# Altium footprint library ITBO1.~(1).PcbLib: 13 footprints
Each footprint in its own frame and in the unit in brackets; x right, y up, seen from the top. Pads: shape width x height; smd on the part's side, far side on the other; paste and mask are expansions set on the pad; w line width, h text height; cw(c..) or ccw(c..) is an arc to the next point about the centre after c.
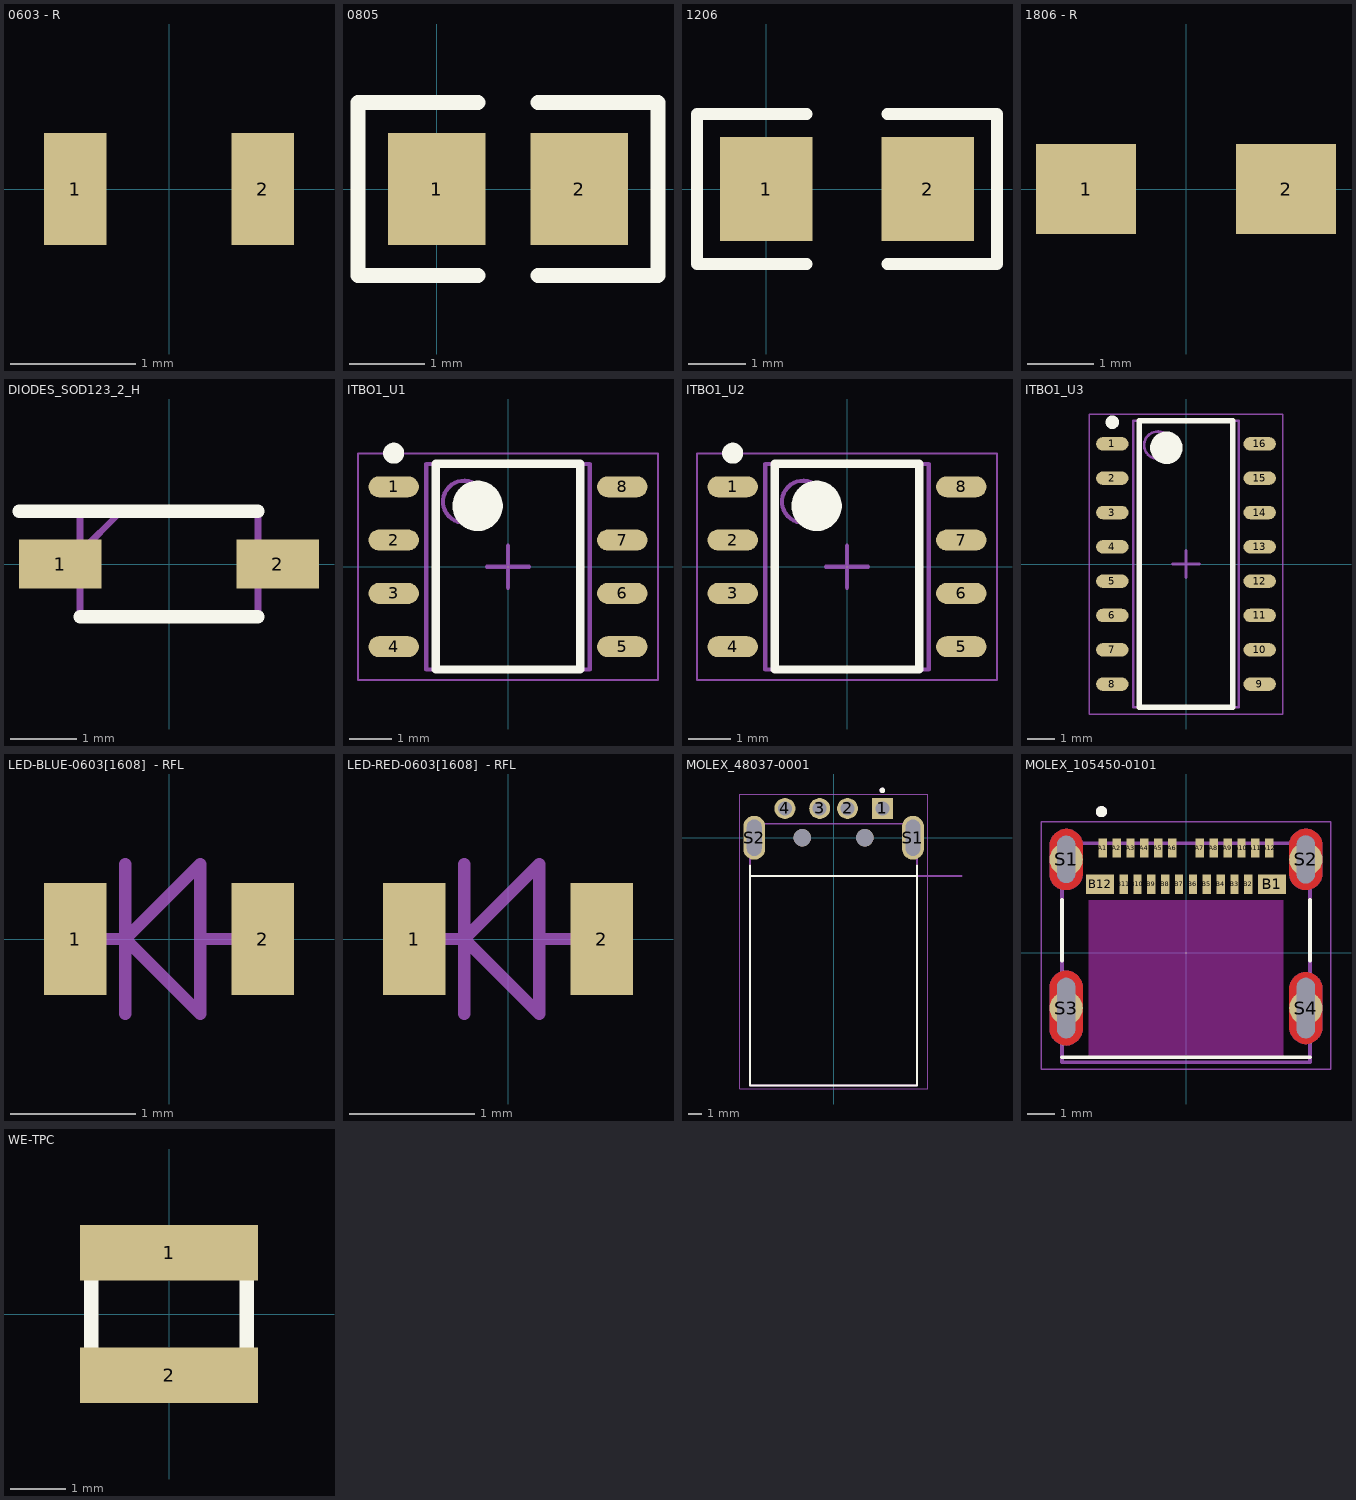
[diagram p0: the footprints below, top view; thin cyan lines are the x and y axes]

## 0603 - R [mm]
pads (2):
  rect 0.5x0.9 smd: 1(-0.75,0) 2(0.75,0)

## 0805 [mm]
pads (2):
  rect 1.3x1.5 smd: 1(0,0) 2(1.9,0)
Top Overlay:
  lines w0.2: 0.55,-1.15 -1.05,-1.15 -1.05,1.15 0.55,1.15 ; 1.35,-1.15 2.95,-1.15 2.95,1.15 1.35,1.15

## 1206 [mm]
pads (2):
  rect 1.6x1.8 smd: 1(0,0) 2(2.8,0)
Top Overlay:
  lines w0.2: 0.7,-1.3 -1.2,-1.3 -1.2,1.3 0.7,1.3 ; 2.1,-1.3 4,-1.3 4,1.3 2.1,1.3

## 1806 - R [mm]
pads (2):
  rect 1.5x1.35 smd: 1(-1.5,0) 2(1.5,0)

## DIODES_SOD123_2_H [mm]
pads (2):
  rect 1.25x0.75 smd: 1(-1.65,0) 2(1.65,0)
Top Overlay:
  lines w0.2: -2.275,0.8 1.35,0.8 ; -1.35,-0.8 1.35,-0.8
Mechanical 15:
  lines w0.1: -1.35,0.175 -0.725,0.8 ; -1.35,-0.8 1.35,-0.8 1.35,0.8 -1.35,0.8 -1.35,-0.8
3D body: height 1.35, standoff 0.1, extent -1.425,-0.85 1.425,0.85

## ITBO1_U1 [mm]
pads (8):
  oval 1.2x0.5 smd: 1(-2.725,1.905) 2(-2.725,0.635) 3(-2.725,-0.635) 4(-2.725,-1.905) 5(2.725,-1.905) 6(2.725,-0.635) 7(2.725,0.635) 8(2.725,1.905)
Top Overlay:
  circle w0.6: c-0.725,1.45 r0.3
  circle w0.25: c-2.725,2.705 r0.125
  lines w0.2: -1.725,-2.45 1.725,-2.45 1.725,2.45 -1.725,2.45 -1.725,-2.45
Mechanical 13:
  circle w0.1: c-1.05,1.55 r0.5
  lines w0.1: -1.95,-2.45 1.95,-2.45 1.95,2.45 -1.95,2.45 -1.95,-2.45
Mechanical 15:
  lines w0.05: -3.575,-2.7 3.575,-2.7 3.575,2.7 -3.575,2.7 -3.575,-2.7
  lines w0.1: -0.5,0 0.5,0 ; 0,-0.5 0,0.5
3D body "ITBO1_U2.step": height 1.25, standoff 0, extent -2.925,-2.45 2.925,2.45

## ITBO1_U2 [mm]
pads (8):
  oval 1.2x0.5 smd: 1(-2.725,1.905) 2(-2.725,0.635) 3(-2.725,-0.635) 4(-2.725,-1.905) 5(2.725,-1.905) 6(2.725,-0.635) 7(2.725,0.635) 8(2.725,1.905)
Top Overlay:
  circle w0.6: c-0.725,1.45 r0.3
  circle w0.25: c-2.725,2.705 r0.125
  lines w0.2: -1.725,-2.45 1.725,-2.45 1.725,2.45 -1.725,2.45 -1.725,-2.45
Mechanical 13:
  circle w0.1: c-1.05,1.55 r0.5
  lines w0.1: -1.95,-2.45 1.95,-2.45 1.95,2.45 -1.95,2.45 -1.95,-2.45
Mechanical 15:
  lines w0.05: -3.575,-2.7 3.575,-2.7 3.575,2.7 -3.575,2.7 -3.575,-2.7
  lines w0.1: -0.5,0 0.5,0 ; 0,-0.5 0,0.5
3D body "ITBO1_U2.step": height 1.25, standoff 0, extent -2.925,-2.45 2.925,2.45

## ITBO1_U3 [mm]
pads (16):
  oval 1.2x0.5 smd: 1(-2.725,4.445) 2(-2.725,3.175) 3(-2.725,1.905) 4(-2.725,0.635) 5(-2.725,-0.635) 6(-2.725,-1.905) 7(-2.725,-3.175) 8(-2.725,-4.445) 9(2.725,-4.445) 10(2.725,-3.175) 11(2.725,-1.905) 12(2.725,-0.635) 13(2.725,0.635) 14(2.725,1.905) 15(2.725,3.175) 16(2.725,4.445)
Top Overlay:
  circle w0.6: c-0.725,4.3 r0.3
  circle w0.25: c-2.725,5.245 r0.125
  lines w0.2: -1.725,-5.3 1.725,-5.3 1.725,5.3 -1.725,5.3 -1.725,-5.3
Mechanical 13:
  circle w0.1: c-1.05,4.4 r0.5
  lines w0.1: -1.95,-5.3 1.95,-5.3 1.95,5.3 -1.95,5.3 -1.95,-5.3
Mechanical 15:
  lines w0.05: -3.575,-5.55 3.575,-5.55 3.575,5.55 -3.575,5.55 -3.575,-5.55
  lines w0.1: -0.5,0 0.5,0 ; 0,-0.5 0,0.5
3D body "SOP127P600-8N.step": height 1.25, standoff 0, extent -2.925,-5.3 2.925,5.3

## LED-BLUE-0603[1608]  - RFL [mm]
pads (2):
  rect 0.5x0.9 smd: 1(-0.75,0) 2(0.75,0)
Mechanical 15:
  lines w0.1: -0.75,0 -0.35,0 ; -0.35,-0.6 -0.35,0.6 ; 0.25,0 0.65,0 ; -0.35,0 0.25,-0.6 0.25,0.6 -0.35,0
3D body "LED0603_blue.step": height 0.6, standoff 0, extent -0.847,-0.419 0.773,0.381

## LED-RED-0603[1608]  - RFL [mm]
pads (2):
  rect 0.5x0.9 smd: 1(-0.75,0) 2(0.75,0)
Mechanical 15:
  lines w0.1: -0.75,0 -0.35,0 ; -0.35,-0.6 -0.35,0.6 ; 0.25,0 0.65,0 ; -0.35,0 0.25,0.6 0.25,-0.6 -0.35,0
3D body "LED0603_red.step": height 0.6, standoff 0, extent -0.847,-0.419 0.773,0.381

## MOLEX_48037-0001 [mm]
pads (8):
  rect 1.508x1.508 hole 1: 1(3.5,2.1)
  round 1.508 hole 1: 2(1,2.1) 3(-1,2.1) 4(-3.5,2.1)
  oval 1.575x3.15 hole 1.05 slot 2.6 at 90 deg: S1(5.7,0) S2(-5.7,0)
  round 1.25 hole 1.25 unplated: ""(-2.25,0) ""(2.25,0)
Top Overlay:
  circle w0.2: c3.5,3.4 r0.1
  lines w0.127: -6,-2 -6,-2.75 ; 6,-2 6,-2.75 ; -6,-2.75 -6,-17.8 6,-17.8 6,-2.75 ; -6,-2.75 6,-2.75
Mechanical 13:
  circle w0.2: c3.5,3.4 r0.1
  lines w0.127: 9.2,-2.75 6,-2.75 ; -6,-2.75 -6,-17.8 6,-17.8 6,-2.75 ; -6,-2.75 6,-2.75 ; -6,-2.75 -6,1 6,1 6,-2.75
  text "PCB EDGE" at 6.28,-2.47 h0.41
Mechanical 15:
  lines w0.05: -6.75,-18.05 6.75,-18.05 6.75,3.11 -6.75,3.11 -6.75,-18.05

## MOLEX_105450-0101 [mm]
pads (28):
  rect 0.3x0.7 smd: A1(-3,3.77) A2(-2.5,3.77) A3(-2,3.77) A4(-1.5,3.77) A5(-1,3.77) A6(-0.5,3.77) A7(0.5,3.77) A8(1,3.77) A9(1.5,3.77) A10(2,3.77) A11(2.5,3.77) A12(3,3.77) B2(2.25,2.47) B3(1.75,2.47) B4(1.25,2.47) B5(0.75,2.47) B6(0.25,2.47) B7(-0.25,2.47) B8(-0.75,2.47) B9(-1.25,2.47) B10(-1.75,2.47) B11(-2.25,2.47)
  rect 1x0.7 smd: B1(3.1,2.47) B12(-3.1,2.47)
  round 1.2 hole 0.65 slot 1.7 at 90 deg mask+0: S1(-4.32,3.36)
  round 1.2 hole 0.65 slot 1.725 at 90 deg mask+0: S2(4.32,3.36)
  round 1.2 hole 0.65 slot 2.175 at 90 deg mask+0: S3(-4.32,-2) S4(4.32,-2)
Top Layer:
  region: -4.289,4.459 -4.257,4.457 -4.226,4.453 -4.195,4.447 -4.165,4.44 -4.135,4.431 -4.105,4.42 -4.076,4.408 -4.048,4.395 -4.02,4.38 -3.993,4.363 -3.967,4.345 -3.942,4.326 -3.919,4.306 -3.896,4.284 -3.874,4.261 -3.854,4.238 -3.835,4.213 -3.817,4.187 -3.8,4.16 -3.785,4.132 -3.772,4.104 -3.76,4.075 -3.749,4.045 -3.74,4.015 -3.733,3.985 -3.727,3.954 -3.723,3.923 -3.721,3.891 -3.72,3.86 -3.72,2.86 -3.721,2.829 -3.723,2.797 -3.727,2.766 -3.733,2.735 -3.74,2.705 -3.749,2.675 -3.76,2.645 -3.772,2.616 -3.785,2.588 -3.8,2.56 -3.817,2.533 -3.835,2.507 -3.854,2.482 -3.874,2.459 -3.896,2.436 -3.919,2.414 -3.942,2.394 -3.967,2.375 -3.993,2.357 -4.02,2.34 -4.048,2.325 -4.076,2.312 -4.105,2.3 -4.135,2.289 -4.165,2.28 -4.195,2.273 -4.226,2.267 -4.257,2.263 -4.289,2.261 -4.32,2.26 -4.355,2.26 -4.385,2.261 -4.415,2.264 -4.445,2.268 -4.474,2.274 -4.504,2.282 -4.532,2.291 -4.561,2.301 -4.588,2.313 -4.615,2.327 -4.641,2.342 -4.667,2.358 -4.691,2.375 -4.715,2.394 -4.738,2.414 -4.759,2.435 -4.779,2.457 -4.799,2.481 -4.816,2.505 -4.833,2.53 -4.848,2.556 -4.862,2.583 -4.875,2.61 -4.886,2.638 -4.895,2.667 -4.903,2.696 -4.91,2.725 -4.915,2.755 -4.918,2.785 -4.92,2.81 -4.92,3.81 -4.92,3.846 -4.919,3.879 -4.916,3.911 -4.911,3.944 -4.904,3.976 -4.896,4.007 -4.886,4.039 -4.875,4.069 -4.862,4.099 -4.847,4.129 -4.831,4.157 -4.814,4.185 -4.795,4.211 -4.774,4.237 -4.752,4.262 -4.73,4.285 -4.705,4.307 -4.68,4.328 -4.654,4.347 -4.626,4.365 -4.598,4.382 -4.569,4.397 -4.539,4.411 -4.509,4.423 -4.478,4.433 -4.446,4.442 -4.414,4.449 -4.382,4.454 -4.35,4.458 -4.32,4.46
  region: 4.351,4.459 4.383,4.457 4.414,4.453 4.445,4.447 4.475,4.44 4.505,4.431 4.535,4.42 4.564,4.408 4.592,4.395 4.62,4.38 4.647,4.363 4.673,4.345 4.698,4.326 4.721,4.306 4.744,4.284 4.766,4.261 4.786,4.238 4.805,4.213 4.823,4.187 4.84,4.16 4.855,4.132 4.868,4.104 4.88,4.075 4.891,4.045 4.9,4.015 4.907,3.985 4.913,3.954 4.917,3.923 4.919,3.891 4.92,3.86 4.92,2.86 4.919,2.829 4.917,2.797 4.913,2.766 4.907,2.735 4.9,2.705 4.891,2.675 4.88,2.645 4.868,2.616 4.855,2.588 4.84,2.56 4.823,2.533 4.805,2.507 4.786,2.482 4.766,2.459 4.744,2.436 4.721,2.414 4.698,2.394 4.673,2.375 4.647,2.357 4.62,2.34 4.592,2.325 4.564,2.312 4.535,2.3 4.505,2.289 4.475,2.28 4.445,2.273 4.414,2.267 4.383,2.263 4.351,2.261 4.32,2.26 4.289,2.261 4.257,2.263 4.226,2.267 4.195,2.273 4.165,2.28 4.135,2.289 4.105,2.3 4.076,2.312 4.048,2.325 4.02,2.34 3.993,2.357 3.967,2.375 3.942,2.394 3.919,2.414 3.896,2.436 3.874,2.459 3.854,2.482 3.835,2.507 3.817,2.533 3.8,2.56 3.785,2.588 3.772,2.616 3.76,2.645 3.749,2.675 3.74,2.705 3.733,2.735 3.727,2.766 3.723,2.797 3.721,2.829 3.72,2.86 3.72,3.86 3.721,3.891 3.723,3.923 3.727,3.954 3.733,3.985 3.74,4.015 3.749,4.045 3.76,4.075 3.772,4.104 3.785,4.132 3.8,4.16 3.817,4.187 3.835,4.213 3.854,4.238 3.874,4.261 3.896,4.284 3.919,4.306 3.942,4.326 3.967,4.345 3.993,4.363 4.02,4.38 4.048,4.395 4.076,4.408 4.105,4.42 4.135,4.431 4.165,4.44 4.195,4.447 4.226,4.453 4.257,4.457 4.289,4.459 4.32,4.46
  region: -4.29,-0.652 -4.258,-0.656 -4.226,-0.661 -4.194,-0.668 -4.162,-0.677 -4.131,-0.687 -4.101,-0.699 -4.071,-0.713 -4.042,-0.728 -4.014,-0.745 -3.986,-0.763 -3.96,-0.782 -3.935,-0.803 -3.91,-0.825 -3.888,-0.848 -3.866,-0.873 -3.845,-0.899 -3.826,-0.925 -3.809,-0.953 -3.793,-0.981 -3.778,-1.011 -3.765,-1.041 -3.754,-1.071 -3.744,-1.103 -3.736,-1.134 -3.729,-1.166 -3.724,-1.199 -3.721,-1.231 -3.72,-1.264 -3.72,-1.3 -3.72,-2.7 -3.72,-2.736 -3.721,-2.769 -3.724,-2.801 -3.729,-2.834 -3.736,-2.866 -3.744,-2.897 -3.754,-2.929 -3.765,-2.959 -3.778,-2.989 -3.793,-3.019 -3.809,-3.047 -3.826,-3.075 -3.845,-3.101 -3.866,-3.127 -3.888,-3.152 -3.91,-3.175 -3.935,-3.197 -3.96,-3.218 -3.986,-3.237 -4.014,-3.255 -4.042,-3.272 -4.071,-3.287 -4.101,-3.301 -4.131,-3.313 -4.162,-3.323 -4.194,-3.332 -4.226,-3.339 -4.258,-3.344 -4.29,-3.348 -4.32,-3.35 -4.35,-3.348 -4.382,-3.344 -4.414,-3.339 -4.446,-3.332 -4.478,-3.323 -4.509,-3.313 -4.539,-3.301 -4.569,-3.287 -4.598,-3.272 -4.626,-3.255 -4.654,-3.237 -4.68,-3.218 -4.705,-3.197 -4.73,-3.175 -4.752,-3.152 -4.774,-3.127 -4.795,-3.101 -4.814,-3.075 -4.831,-3.047 -4.847,-3.019 -4.862,-2.989 -4.875,-2.959 -4.886,-2.929 -4.896,-2.897 -4.904,-2.866 -4.911,-2.834 -4.916,-2.801 -4.919,-2.769 -4.92,-2.736 -4.92,-2.7 -4.92,-1.3 -4.92,-1.264 -4.919,-1.231 -4.916,-1.199 -4.911,-1.166 -4.904,-1.134 -4.896,-1.103 -4.886,-1.071 -4.875,-1.041 -4.862,-1.011 -4.847,-0.981 -4.831,-0.953 -4.814,-0.925 -4.795,-0.899 -4.774,-0.873 -4.752,-0.848 -4.73,-0.825 -4.705,-0.803 -4.68,-0.782 -4.654,-0.763 -4.626,-0.745 -4.598,-0.728 -4.569,-0.713 -4.539,-0.699 -4.509,-0.687 -4.478,-0.677 -4.446,-0.668 -4.414,-0.661 -4.382,-0.656 -4.35,-0.652 -4.32,-0.65
  region: 4.35,-0.702 4.382,-0.706 4.414,-0.711 4.446,-0.718 4.478,-0.727 4.509,-0.737 4.539,-0.749 4.569,-0.763 4.598,-0.778 4.626,-0.795 4.654,-0.813 4.68,-0.832 4.705,-0.853 4.73,-0.875 4.752,-0.898 4.774,-0.923 4.795,-0.949 4.814,-0.975 4.831,-1.003 4.847,-1.031 4.862,-1.061 4.875,-1.091 4.886,-1.121 4.896,-1.153 4.904,-1.184 4.911,-1.216 4.916,-1.249 4.919,-1.281 4.92,-1.314 4.92,-1.35 4.92,-2.65 4.92,-2.686 4.919,-2.719 4.916,-2.751 4.911,-2.784 4.904,-2.816 4.896,-2.847 4.886,-2.879 4.875,-2.909 4.862,-2.939 4.847,-2.969 4.831,-2.997 4.814,-3.025 4.795,-3.051 4.774,-3.077 4.752,-3.102 4.73,-3.125 4.705,-3.147 4.68,-3.168 4.654,-3.187 4.626,-3.205 4.598,-3.222 4.569,-3.237 4.539,-3.251 4.509,-3.263 4.478,-3.273 4.446,-3.282 4.414,-3.289 4.382,-3.294 4.35,-3.298 4.32,-3.3 4.29,-3.298 4.258,-3.294 4.226,-3.289 4.194,-3.282 4.162,-3.273 4.131,-3.263 4.101,-3.251 4.071,-3.237 4.042,-3.222 4.014,-3.205 3.986,-3.187 3.96,-3.168 3.935,-3.147 3.91,-3.125 3.888,-3.102 3.866,-3.077 3.845,-3.051 3.826,-3.025 3.809,-2.997 3.793,-2.969 3.778,-2.939 3.765,-2.909 3.754,-2.879 3.744,-2.847 3.736,-2.816 3.729,-2.784 3.724,-2.751 3.721,-2.719 3.72,-2.686 3.72,-2.65 3.72,-1.35 3.72,-1.314 3.721,-1.281 3.724,-1.249 3.729,-1.216 3.736,-1.184 3.744,-1.153 3.754,-1.121 3.765,-1.091 3.778,-1.061 3.793,-1.031 3.809,-1.003 3.826,-0.975 3.845,-0.949 3.866,-0.923 3.888,-0.898 3.91,-0.875 3.935,-0.853 3.96,-0.832 3.986,-0.813 4.014,-0.795 4.042,-0.778 4.071,-0.763 4.101,-0.749 4.131,-0.737 4.162,-0.727 4.194,-0.718 4.226,-0.711 4.258,-0.706 4.29,-0.702 4.32,-0.7
Bottom Layer:
  region: -4.289,4.459 -4.257,4.457 -4.226,4.453 -4.195,4.447 -4.165,4.44 -4.135,4.431 -4.105,4.42 -4.076,4.408 -4.048,4.395 -4.02,4.38 -3.993,4.363 -3.967,4.345 -3.942,4.326 -3.919,4.306 -3.896,4.284 -3.874,4.261 -3.854,4.238 -3.835,4.213 -3.817,4.187 -3.8,4.16 -3.785,4.132 -3.772,4.104 -3.76,4.075 -3.749,4.045 -3.74,4.015 -3.733,3.985 -3.727,3.954 -3.723,3.923 -3.721,3.891 -3.72,3.86 -3.72,2.86 -3.721,2.829 -3.723,2.797 -3.727,2.766 -3.733,2.735 -3.74,2.705 -3.749,2.675 -3.76,2.645 -3.772,2.616 -3.785,2.588 -3.8,2.56 -3.817,2.533 -3.835,2.507 -3.854,2.482 -3.874,2.459 -3.896,2.436 -3.919,2.414 -3.942,2.394 -3.967,2.375 -3.993,2.357 -4.02,2.34 -4.048,2.325 -4.076,2.312 -4.105,2.3 -4.135,2.289 -4.165,2.28 -4.195,2.273 -4.226,2.267 -4.257,2.263 -4.289,2.261 -4.32,2.26 -4.355,2.26 -4.385,2.261 -4.415,2.264 -4.445,2.268 -4.474,2.274 -4.504,2.282 -4.532,2.291 -4.561,2.301 -4.588,2.313 -4.615,2.327 -4.641,2.342 -4.667,2.358 -4.691,2.375 -4.715,2.394 -4.738,2.414 -4.759,2.435 -4.779,2.457 -4.799,2.481 -4.816,2.505 -4.833,2.53 -4.848,2.556 -4.862,2.583 -4.875,2.61 -4.886,2.638 -4.895,2.667 -4.903,2.696 -4.91,2.725 -4.915,2.755 -4.918,2.785 -4.92,2.81 -4.92,3.81 -4.92,3.846 -4.919,3.879 -4.916,3.911 -4.911,3.944 -4.904,3.976 -4.896,4.007 -4.886,4.039 -4.875,4.069 -4.862,4.099 -4.847,4.129 -4.831,4.157 -4.814,4.185 -4.795,4.211 -4.774,4.237 -4.752,4.262 -4.73,4.285 -4.705,4.307 -4.68,4.328 -4.654,4.347 -4.626,4.365 -4.598,4.382 -4.569,4.397 -4.539,4.411 -4.509,4.423 -4.478,4.433 -4.446,4.442 -4.414,4.449 -4.382,4.454 -4.35,4.458 -4.32,4.46
  region: 4.351,4.459 4.383,4.457 4.414,4.453 4.445,4.447 4.475,4.44 4.505,4.431 4.535,4.42 4.564,4.408 4.592,4.395 4.62,4.38 4.647,4.363 4.673,4.345 4.698,4.326 4.721,4.306 4.744,4.284 4.766,4.261 4.786,4.238 4.805,4.213 4.823,4.187 4.84,4.16 4.855,4.132 4.868,4.104 4.88,4.075 4.891,4.045 4.9,4.015 4.907,3.985 4.913,3.954 4.917,3.923 4.919,3.891 4.92,3.86 4.92,2.86 4.919,2.829 4.917,2.797 4.913,2.766 4.907,2.735 4.9,2.705 4.891,2.675 4.88,2.645 4.868,2.616 4.855,2.588 4.84,2.56 4.823,2.533 4.805,2.507 4.786,2.482 4.766,2.459 4.744,2.436 4.721,2.414 4.698,2.394 4.673,2.375 4.647,2.357 4.62,2.34 4.592,2.325 4.564,2.312 4.535,2.3 4.505,2.289 4.475,2.28 4.445,2.273 4.414,2.267 4.383,2.263 4.351,2.261 4.32,2.26 4.289,2.261 4.257,2.263 4.226,2.267 4.195,2.273 4.165,2.28 4.135,2.289 4.105,2.3 4.076,2.312 4.048,2.325 4.02,2.34 3.993,2.357 3.967,2.375 3.942,2.394 3.919,2.414 3.896,2.436 3.874,2.459 3.854,2.482 3.835,2.507 3.817,2.533 3.8,2.56 3.785,2.588 3.772,2.616 3.76,2.645 3.749,2.675 3.74,2.705 3.733,2.735 3.727,2.766 3.723,2.797 3.721,2.829 3.72,2.86 3.72,3.86 3.721,3.891 3.723,3.923 3.727,3.954 3.733,3.985 3.74,4.015 3.749,4.045 3.76,4.075 3.772,4.104 3.785,4.132 3.8,4.16 3.817,4.187 3.835,4.213 3.854,4.238 3.874,4.261 3.896,4.284 3.919,4.306 3.942,4.326 3.967,4.345 3.993,4.363 4.02,4.38 4.048,4.395 4.076,4.408 4.105,4.42 4.135,4.431 4.165,4.44 4.195,4.447 4.226,4.453 4.257,4.457 4.289,4.459 4.32,4.46
  region: -4.29,-0.652 -4.258,-0.656 -4.226,-0.661 -4.194,-0.668 -4.162,-0.677 -4.131,-0.687 -4.101,-0.699 -4.071,-0.713 -4.042,-0.728 -4.014,-0.745 -3.986,-0.763 -3.96,-0.782 -3.935,-0.803 -3.91,-0.825 -3.888,-0.848 -3.866,-0.873 -3.845,-0.899 -3.826,-0.925 -3.809,-0.953 -3.793,-0.981 -3.778,-1.011 -3.765,-1.041 -3.754,-1.071 -3.744,-1.103 -3.736,-1.134 -3.729,-1.166 -3.724,-1.199 -3.721,-1.231 -3.72,-1.264 -3.72,-1.3 -3.72,-2.7 -3.72,-2.736 -3.721,-2.769 -3.724,-2.801 -3.729,-2.834 -3.736,-2.866 -3.744,-2.897 -3.754,-2.929 -3.765,-2.959 -3.778,-2.989 -3.793,-3.019 -3.809,-3.047 -3.826,-3.075 -3.845,-3.101 -3.866,-3.127 -3.888,-3.152 -3.91,-3.175 -3.935,-3.197 -3.96,-3.218 -3.986,-3.237 -4.014,-3.255 -4.042,-3.272 -4.071,-3.287 -4.101,-3.301 -4.131,-3.313 -4.162,-3.323 -4.194,-3.332 -4.226,-3.339 -4.258,-3.344 -4.29,-3.348 -4.32,-3.35 -4.35,-3.348 -4.382,-3.344 -4.414,-3.339 -4.446,-3.332 -4.478,-3.323 -4.509,-3.313 -4.539,-3.301 -4.569,-3.287 -4.598,-3.272 -4.626,-3.255 -4.654,-3.237 -4.68,-3.218 -4.705,-3.197 -4.73,-3.175 -4.752,-3.152 -4.774,-3.127 -4.795,-3.101 -4.814,-3.075 -4.831,-3.047 -4.847,-3.019 -4.862,-2.989 -4.875,-2.959 -4.886,-2.929 -4.896,-2.897 -4.904,-2.866 -4.911,-2.834 -4.916,-2.801 -4.919,-2.769 -4.92,-2.736 -4.92,-2.7 -4.92,-1.3 -4.92,-1.264 -4.919,-1.231 -4.916,-1.199 -4.911,-1.166 -4.904,-1.134 -4.896,-1.103 -4.886,-1.071 -4.875,-1.041 -4.862,-1.011 -4.847,-0.981 -4.831,-0.953 -4.814,-0.925 -4.795,-0.899 -4.774,-0.873 -4.752,-0.848 -4.73,-0.825 -4.705,-0.803 -4.68,-0.782 -4.654,-0.763 -4.626,-0.745 -4.598,-0.728 -4.569,-0.713 -4.539,-0.699 -4.509,-0.687 -4.478,-0.677 -4.446,-0.668 -4.414,-0.661 -4.382,-0.656 -4.35,-0.652 -4.32,-0.65
  region: 4.35,-0.702 4.382,-0.706 4.414,-0.711 4.446,-0.718 4.478,-0.727 4.509,-0.737 4.539,-0.749 4.569,-0.763 4.598,-0.778 4.626,-0.795 4.654,-0.813 4.68,-0.832 4.705,-0.853 4.73,-0.875 4.752,-0.898 4.774,-0.923 4.795,-0.949 4.814,-0.975 4.831,-1.003 4.847,-1.031 4.862,-1.061 4.875,-1.091 4.886,-1.121 4.896,-1.153 4.904,-1.184 4.911,-1.216 4.916,-1.249 4.919,-1.281 4.92,-1.314 4.92,-1.35 4.92,-2.65 4.92,-2.686 4.919,-2.719 4.916,-2.751 4.911,-2.784 4.904,-2.816 4.896,-2.847 4.886,-2.879 4.875,-2.909 4.862,-2.939 4.847,-2.969 4.831,-2.997 4.814,-3.025 4.795,-3.051 4.774,-3.077 4.752,-3.102 4.73,-3.125 4.705,-3.147 4.68,-3.168 4.654,-3.187 4.626,-3.205 4.598,-3.222 4.569,-3.237 4.539,-3.251 4.509,-3.263 4.478,-3.273 4.446,-3.282 4.414,-3.289 4.382,-3.294 4.35,-3.298 4.32,-3.3 4.29,-3.298 4.258,-3.294 4.226,-3.289 4.194,-3.282 4.162,-3.273 4.131,-3.263 4.101,-3.251 4.071,-3.237 4.042,-3.222 4.014,-3.205 3.986,-3.187 3.96,-3.168 3.935,-3.147 3.91,-3.125 3.888,-3.102 3.866,-3.077 3.845,-3.051 3.826,-3.025 3.809,-2.997 3.793,-2.969 3.778,-2.939 3.765,-2.909 3.754,-2.879 3.744,-2.847 3.736,-2.816 3.729,-2.784 3.724,-2.751 3.721,-2.719 3.72,-2.686 3.72,-2.65 3.72,-1.35 3.72,-1.314 3.721,-1.281 3.724,-1.249 3.729,-1.216 3.736,-1.184 3.744,-1.153 3.754,-1.121 3.765,-1.091 3.778,-1.061 3.793,-1.031 3.809,-1.003 3.826,-0.975 3.845,-0.949 3.866,-0.923 3.888,-0.898 3.91,-0.875 3.935,-0.853 3.96,-0.832 3.986,-0.813 4.014,-0.795 4.042,-0.778 4.071,-0.763 4.101,-0.749 4.131,-0.737 4.162,-0.727 4.194,-0.718 4.226,-0.711 4.258,-0.706 4.29,-0.702 4.32,-0.7
Top Overlay:
  circle w0.2: c-3.048,5.08 r0.1
  lines w0.127: -4.47,-3.77 4.47,-3.77 ; -4.47,-0.3 -4.47,1.9 ; 4.47,-0.3 4.47,1.9
Top Solder:
  drawing of 4 lines, arcs and shapes, not listed
Bottom Solder:
  drawing of 4 lines, arcs and shapes, not listed
Keep-Out Layer:
  region: 3.5,-3.77 -3.5,-3.77 -3.5,1.88 3.5,1.88
Mechanical 13:
  circle w0.2: c-3.048,5.08 r0.1
  lines w0.127: -4.47,-3.95 4.47,-3.95 4.47,3.95 -4.47,3.95 -4.47,-3.95
Mechanical 15:
  lines w0.05: -5.22,-4.2 5.22,-4.2 5.22,4.71 -5.22,4.71 -5.22,-4.2

## WE-TPC [mm]
pads (2):
  rect 3.2x1 smd: 1(0,1.1) 2(0,-1.1)
Top Overlay:
  lines w0.254: -1.4,-1.4 1.4,-1.4 1.4,1.4 -1.4,1.4 -1.4,-1.4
